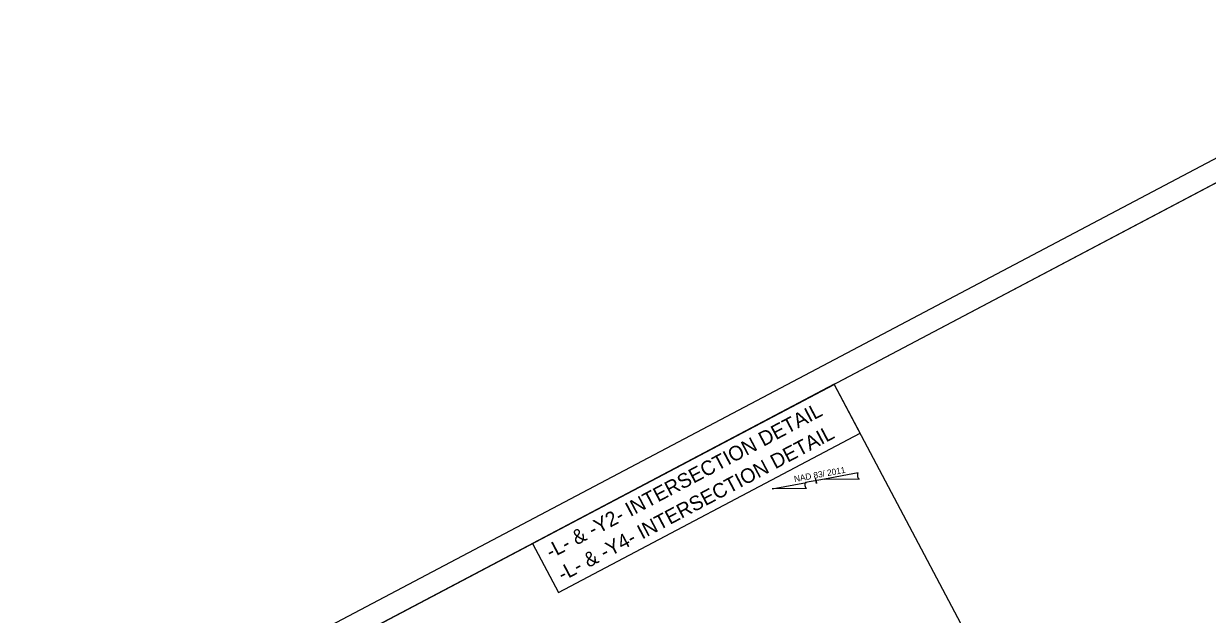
# Model space of a CAD drawing. Extents: x 1487555 to 1489555, y 497613 to 499367.
# Drawn here: x 1487555 to 1488773, y 498759 to 499367 of the extents above; entities that cross this region are included whole.
import ezdxf

# ---------------------------------------------------------------- set-up
doc = ezdxf.new("R2010")
doc.units = 0
for name, color, linetype in [('Prop Grid Mask', 7, 'Continuous'), ('Prop Horizontal Alignment Curve and Spiral Data', 7, 'Continuous'), ('Prop North Arrow NAD83 for Plan Sheets CELL', 7, 'Continuous'), ('Sheet Plan CELL', 7, 'Continuous'), ('Sheet Plot Border Outside CELL', 7, 'Continuous')]:
    doc.layers.add(name, color=color, linetype=linetype)

msp = doc.modelspace()

# ---------------------------------------------------------------- linework, layer by layer
at = {"layer": 'Prop Grid Mask'}
msp.add_lwpolyline([(1488105, 498781.6), (1488415.3, 498945.5), (1488388.7, 498995.9), (1488078.4, 498832)], close=True, dxfattribs=at)
at = {"layer": 'Prop North Arrow NAD83 for Plan Sheets CELL'}
for p, q in [((1488378.6, 498898.3), (1488359.2, 498894.7)), ((1488370.5, 498893.8), (1488369.5, 498899.7)), ((1488370.1, 498896.4), (1488370.5, 498893.8)), ((1488413.3, 498904.7), (1488378.6, 498898.3)), ((1488378.6, 498898.3), (1488414.5, 498898.6)), ((1488325, 498888.4), (1488360.3, 498894.9)), ((1488360.3, 498888.7), (1488325, 498888.4)), ((1488325, 498888.4), (1488325, 498888.4)), ((1488325, 498888.4), (1488325, 498888.4)), ((1488360.3, 498894.9), (1488359.3, 498894.8)), ((1488370.5, 498893.8), (1488370.6, 498893.7))]:
    msp.add_line(p, q, dxfattribs=at)
for centre, start_param, end_param in [((1488414.1, 498901.7), 0.201328, 3.141593), ((1488360.1, 498891.8), 0.216388, 2.908219)]:
    msp.add_ellipse(centre, major_axis=(-0.55, 3.12), ratio=0.461098, start_param=start_param, end_param=end_param, dxfattribs=at)
at = {"layer": 'Sheet Plan CELL'}
for points in [[(1489039.1, 499339.2), (1487712.6, 498638.8), (1488202.9, 497710.3), (1489529.3, 498410.7)], [(1488202.9, 497710.3), (1487712.6, 498638.8), (1488862.1, 499245.8), (1488932.2, 499113.1), (1489109.1, 499206.5), (1489529.3, 498410.7)], [(1487712.6, 498638.8), (1488388.8, 498995.8), (1488586.4, 498621.6), (1487910.2, 498264.6)]]:
    msp.add_lwpolyline(points, close=True, dxfattribs=at)
at = {"layer": 'Sheet Plot Border Outside CELL'}
msp.add_lwpolyline([(1488066.1, 497612.7), (1489554.9, 498398.7), (1489043.6, 499367), (1487554.9, 498581)], close=True, dxfattribs=at)

# ---------------------------------------------------------------- texts
at = {"layer": 'Prop Horizontal Alignment Curve and Spiral Data'}
for s, p in [('-L- & -Y2- INTERSECTION DETAIL', (1488097.1, 498816)), ('-L- & -Y4- INTERSECTION DETAIL', (1488109.3, 498792.8))]:
    msp.add_text(s, height=15, rotation=27.8351, dxfattribs=at).set_placement(p)
at = {"layer": 'Prop North Arrow NAD83 for Plan Sheets CELL'}
msp.add_text('NAD 83/ 2011', height=6.375, rotation=10.4301, dxfattribs=at).set_placement((1488348, 498895.2))

doc.saveas('drawing.dxf')
